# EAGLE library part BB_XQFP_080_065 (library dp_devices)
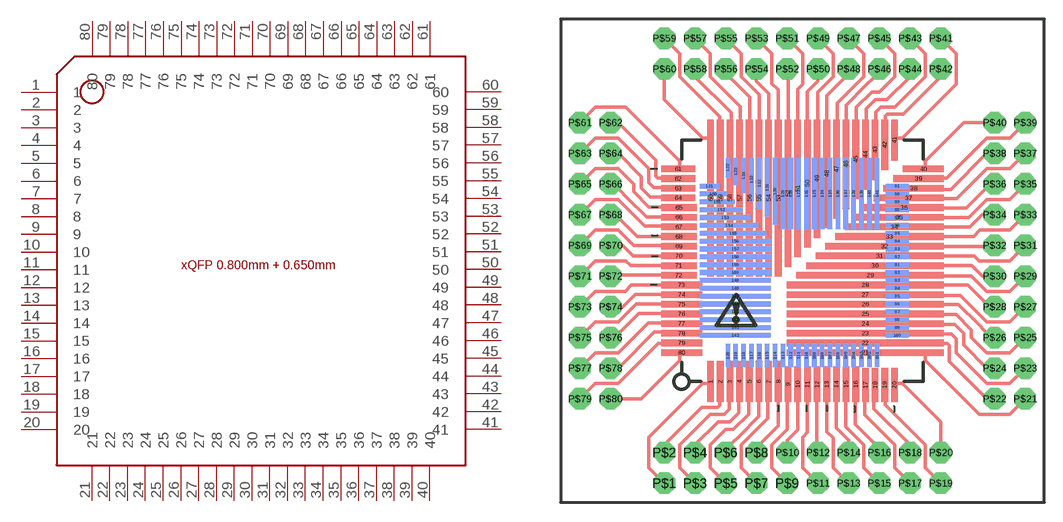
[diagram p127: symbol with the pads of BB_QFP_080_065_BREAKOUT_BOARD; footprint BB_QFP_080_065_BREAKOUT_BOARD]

Designator prefix IC

## BB_XQFP_080_065  [BB_QFP_080_065_BREAKOUT_BOARD]
1  1
2  2
3  3
4  4
5  5
6  6
7  7
8  8
9  9
10  10
11  11
12  12
13  13
14  14
15  15
16  16
17  17
18  18
19  19
20  20
21  21
22  22
23  23
24  24
25  25
26  26
27  27
28  28
29  29
30  30
31  31
32  32
33  33
34  34
35  35
36  36
37  37
38  38
39  39
40  40
41  41
42  42
43  43
44  44
45  45
46  46
47  47
48  48
49  49
50  50
51  51
52  52
53  53
54  54
55  55
56  56
57  57
58  58
59  59
60  60
61  61
62  62
63  63
64  64
65  65
66  66
67  67
68  68
69  69
70  70
71  71
72  72
73  73
74  74
75  75
76  76
77  77
78  78
79  79
80  80

## Footprint BB_QFP_080_065_BREAKOUT_BOARD (pad centres in mm)
QFP 0.65 mm pitch 52p (10mm sq) 80p (14mm sq) QFP 0.8 mm pitch 32p (7mm sq) 44p (10mm sq) 64p (14mm sq) 80p (16.5mm sq) CC-BY-SA
smd 0.55 x 3.405: 1 -7.6,-9.998; 2 -6.8,-9.998; 3 -6,-9.998; 4 -5.2,-9.998; 5 -4.4,-9.998; 6 -3.6,-9.998; 7 -2.8,-9.998; 8 -2,-9.998; 41 7.6,9.997
smd 0.55 x 2.95: 9 -1.2,-10.225; 10 -0.4,-10.225; 11 0.4,-10.225; 12 1.2,-10.225; 13 2,-10.225; 14 2.8,-10.225; 15 3.6,-10.225; 16 4.4,-10.225
smd 0.55 x 2.85: 17 5.2,-10.275; 18 6,-10.275; 19 6.8,-10.275; 20 7.6,-10.275
smd 13.005 x 0.55: 21 5.197,-7.6; 22 5.197,-6.8; 23 5.197,-6; 24 5.197,-5.2; 25 5.197,-4.4; 26 5.197,-3.6; 27 5.197,-2.8; 28 5.197,-2
smd 12.205 x 0.55: 29 5.597,-1.2
smd 11.405 x 0.55: 30 5.997,-0.4
smd 10.605 x 0.55: 31 6.397,0.4
smd 9.805 x 0.55: 32 6.797,1.2
smd 9.005 x 0.55: 33 7.197,2
smd 8.205 x 0.55: 34 7.597,2.8
smd 7.405 x 0.55: 35 7.997,3.6
smd 6.605 x 0.55: 36 8.397,4.4
smd 5.805 x 0.55: 37 8.797,5.2
smd 5.005 x 0.55: 38 9.197,6
smd 4.205 x 0.55: 39 9.597,6.8
smd 3.405 x 0.55: 40 9.997,7.6; 73 -9.998,-2; 74 -9.998,-2.8; 75 -9.998,-3.6; 76 -9.998,-4.4; 77 -9.998,-5.2; 78 -9.998,-6; 79 -9.998,-6.8; 80 -9.998,-7.6
smd 0.55 x 4.205: 42 6.8,9.597
smd 0.55 x 5.005: 43 6,9.197
smd 0.55 x 5.805: 44 5.2,8.797
smd 0.55 x 6.605: 45 4.4,8.397
smd 0.55 x 7.405: 46 3.6,7.997
smd 0.55 x 8.205: 47 2.8,7.597
smd 0.55 x 9.005: 48 2,7.197
smd 0.55 x 9.805: 49 1.2,6.797
smd 0.55 x 10.605: 50 0.4,6.397
smd 0.55 x 11.405: 51 -0.4,5.997
smd 0.55 x 12.205: 52 -1.2,5.597
smd 0.55 x 13.005: 53 -2,5.198; 54 -2.8,5.198; 55 -3.6,5.198; 56 -4.4,5.198; 57 -5.2,5.198; 58 -6,5.198; 59 -6.8,5.198; 60 -7.6,5.198
smd 2.85 x 0.55: 61 -10.275,7.6; 62 -10.275,6.8; 63 -10.275,6; 64 -10.275,5.2
smd 2.95 x 0.55: 65 -10.225,4.4; 66 -10.225,3.6; 67 -10.225,2.8; 68 -10.225,2; 69 -10.225,1.2; 70 -10.225,0.4; 71 -10.225,-0.4; 72 -10.225,-1.2
smd 1.875 x 0.38 bottom: 81 7.838,-0.325; 82 7.838,0.325; 83 7.838,0.975; 84 7.838,1.625; 85 7.838,2.275; 86 7.838,2.925; 87 7.838,3.575; 88 7.838,4.225; 89 7.838,4.875; 90 7.838,5.525; 91 7.838,6.175; 92 7.838,-0.975; 93 7.838,-1.625; 94 7.838,-2.275; 95 7.838,-2.925; 96 7.838,-3.575; 97 7.838,-4.225; 98 7.838,-4.875; 99 7.838,-5.525; 100 7.838,-6.175
smd 0.38 x 1.875 bottom: 101 6.175,-7.838; 102 5.525,-7.838; 103 4.875,-7.838; 104 4.225,-7.838; 105 3.575,-7.838; 106 2.925,-7.838; 107 2.275,-7.838; 108 1.625,-7.838; 109 0.975,-7.838; 110 0.325,-7.838; 111 -0.325,-7.838; 112 -0.975,-7.838; 113 -1.625,-7.838; 114 -2.275,-7.838; 115 -2.925,-7.838; 116 -3.575,-7.838; 117 -4.225,-7.838; 118 -4.875,-7.838; 119 -5.525,-7.838; 120 -6.175,-7.838
smd 1.6 x 0.38 bottom: 121 -7.7,6.175
smd 0.38 x 1.6 bottom: 122 -6.175,7.7
smd 0.38 x 2.25 bottom: 123 -5.525,7.375
smd 0.38 x 5.875 bottom: 124 1.625,5.563; 125 0.975,5.563; 126 0.325,5.563; 127 -0.325,5.563; 128 -0.975,5.563; 129 -1.625,5.563; 135 2.275,5.563; 136 2.925,5.563; 137 3.575,5.563; 138 4.225,5.563; 139 4.875,5.563; 140 5.525,5.563; 141 6.175,5.563
smd 0.38 x 5.5 bottom: 130 -2.275,5.75
smd 0.38 x 4.85 bottom: 131 -2.925,6.075
smd 0.38 x 4.2 bottom: 132 -3.575,6.4
smd 0.38 x 3.55 bottom: 133 -4.225,6.725
smd 0.38 x 2.9 bottom: 134 -4.875,7.05
smd 5.875 x 0.38 bottom: 142 -5.563,-6.175; 143 -5.563,-5.525; 144 -5.563,-4.875; 145 -5.563,-4.225; 146 -5.563,-3.575; 147 -5.563,-2.925; 148 -5.563,-2.275; 149 -5.563,-1.625; 156 -5.563,1.625; 157 -5.563,0.975; 158 -5.563,0.325; 159 -5.563,-0.325; 160 -5.563,-0.975
smd 2.25 x 0.38 bottom: 150 -7.375,5.525
smd 2.9 x 0.38 bottom: 151 -7.05,4.875
smd 3.55 x 0.38 bottom: 152 -6.725,4.225
smd 4.2 x 0.38 bottom: 153 -6.4,3.575
smd 4.85 x 0.38 bottom: 154 -6.075,2.925
smd 5.5 x 0.38 bottom: 155 -5.75,2.275
drill 1.016 pad 1.778 octagon: P$1 -11.43,-18.415; P$2 -11.43,-15.875; P$3 -8.89,-18.415; P$4 -8.89,-15.875; P$5 -6.35,-18.415; P$6 -6.35,-15.875; P$7 -3.81,-18.415; P$8 -3.81,-15.875; P$9 -1.27,-18.415; P$10 -1.27,-15.875; P$11 1.27,-18.415; P$12 1.27,-15.875; P$13 3.81,-18.415; P$14 3.81,-15.875; P$15 6.35,-18.415; P$16 6.35,-15.875; P$17 8.89,-18.415; P$18 8.89,-15.875; P$19 11.43,-18.415; P$20 11.43,-15.875; P$21 18.415,-11.43; P$22 15.875,-11.43; P$23 18.415,-8.89; P$24 15.875,-8.89; P$25 18.415,-6.35; P$26 15.875,-6.35; P$27 18.415,-3.81; P$28 15.875,-3.81; P$29 18.415,-1.27; P$30 15.875,-1.27; P$31 18.415,1.27; P$32 15.875,1.27; P$33 18.415,3.81; P$34 15.875,3.81; P$35 18.415,6.35; P$36 15.875,6.35; P$37 18.415,8.89; P$38 15.875,8.89; P$39 18.415,11.43; P$40 15.875,11.43; P$41 11.43,18.415; P$42 11.43,15.875; P$43 8.89,18.415; P$44 8.89,15.875; P$45 6.35,18.415; P$46 6.35,15.875; P$47 3.81,18.415; P$48 3.81,15.875; P$49 1.27,18.415; P$50 1.27,15.875; P$51 -1.27,18.415; P$52 -1.27,15.875; P$53 -3.81,18.415; P$54 -3.81,15.875; P$55 -6.35,18.415; P$56 -6.35,15.875; P$57 -8.89,18.415; P$58 -8.89,15.875; P$59 -11.43,18.415; P$60 -11.43,15.875; P$61 -18.415,11.43; P$62 -15.875,11.43; P$63 -18.415,8.89; P$64 -15.875,8.89; P$65 -18.415,6.35; P$66 -15.875,6.35; P$67 -18.415,3.81; P$68 -15.875,3.81; P$69 -18.415,1.27; P$70 -15.875,1.27; P$71 -18.415,-1.27; P$72 -15.875,-1.27; P$73 -18.415,-3.81; P$74 -15.875,-3.81; P$75 -18.415,-6.35; P$76 -15.875,-6.35; P$77 -18.415,-8.89; P$78 -15.875,-8.89; P$79 -18.415,-11.43; P$80 -15.875,-11.43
